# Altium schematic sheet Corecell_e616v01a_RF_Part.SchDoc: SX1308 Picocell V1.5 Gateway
size A2; DrawnBy: EMr; DocumentNumber: 2; SheetNumber: 2; SheetTotal: 3; PageSetup: Record=PageOptions¦CenterHorizontal=True¦CenterVertical=True¦PrintScale=0.47¦XCorrection=1.00¦YCorrection=1.00¦PrintKind=0¦BorderSize=5000000¦LeftOffset=0¦BottomOffset=0¦Orientation=2¦PaperLength=1000¦PaperWidth=1000¦Scale=100¦PaperSource=7¦PrintQuality=-4¦MediaType=1¦DitherType=10¦PaperKind=Letter¦PrintScaleMode=1
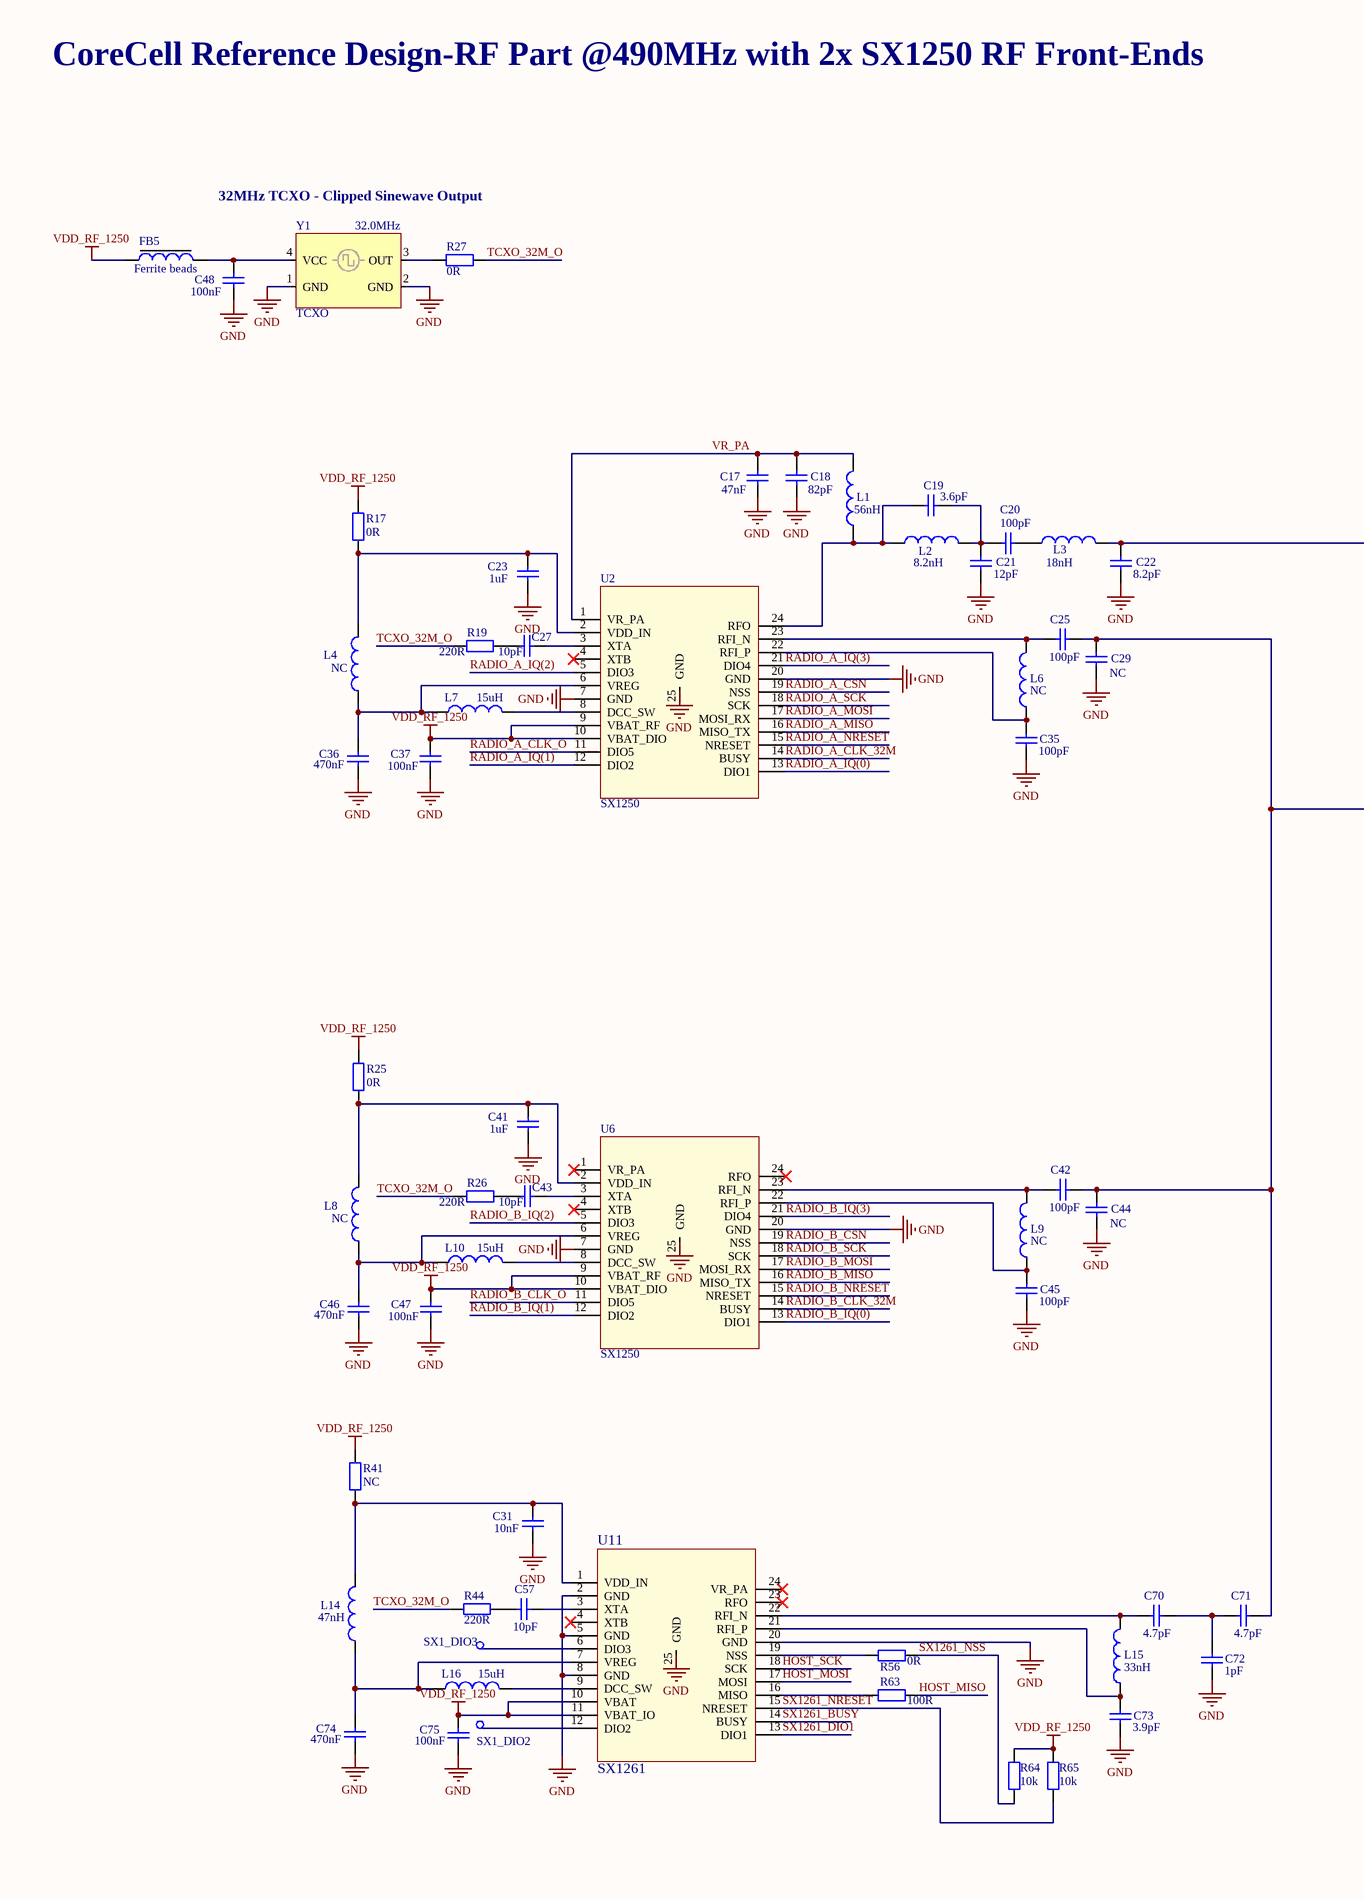
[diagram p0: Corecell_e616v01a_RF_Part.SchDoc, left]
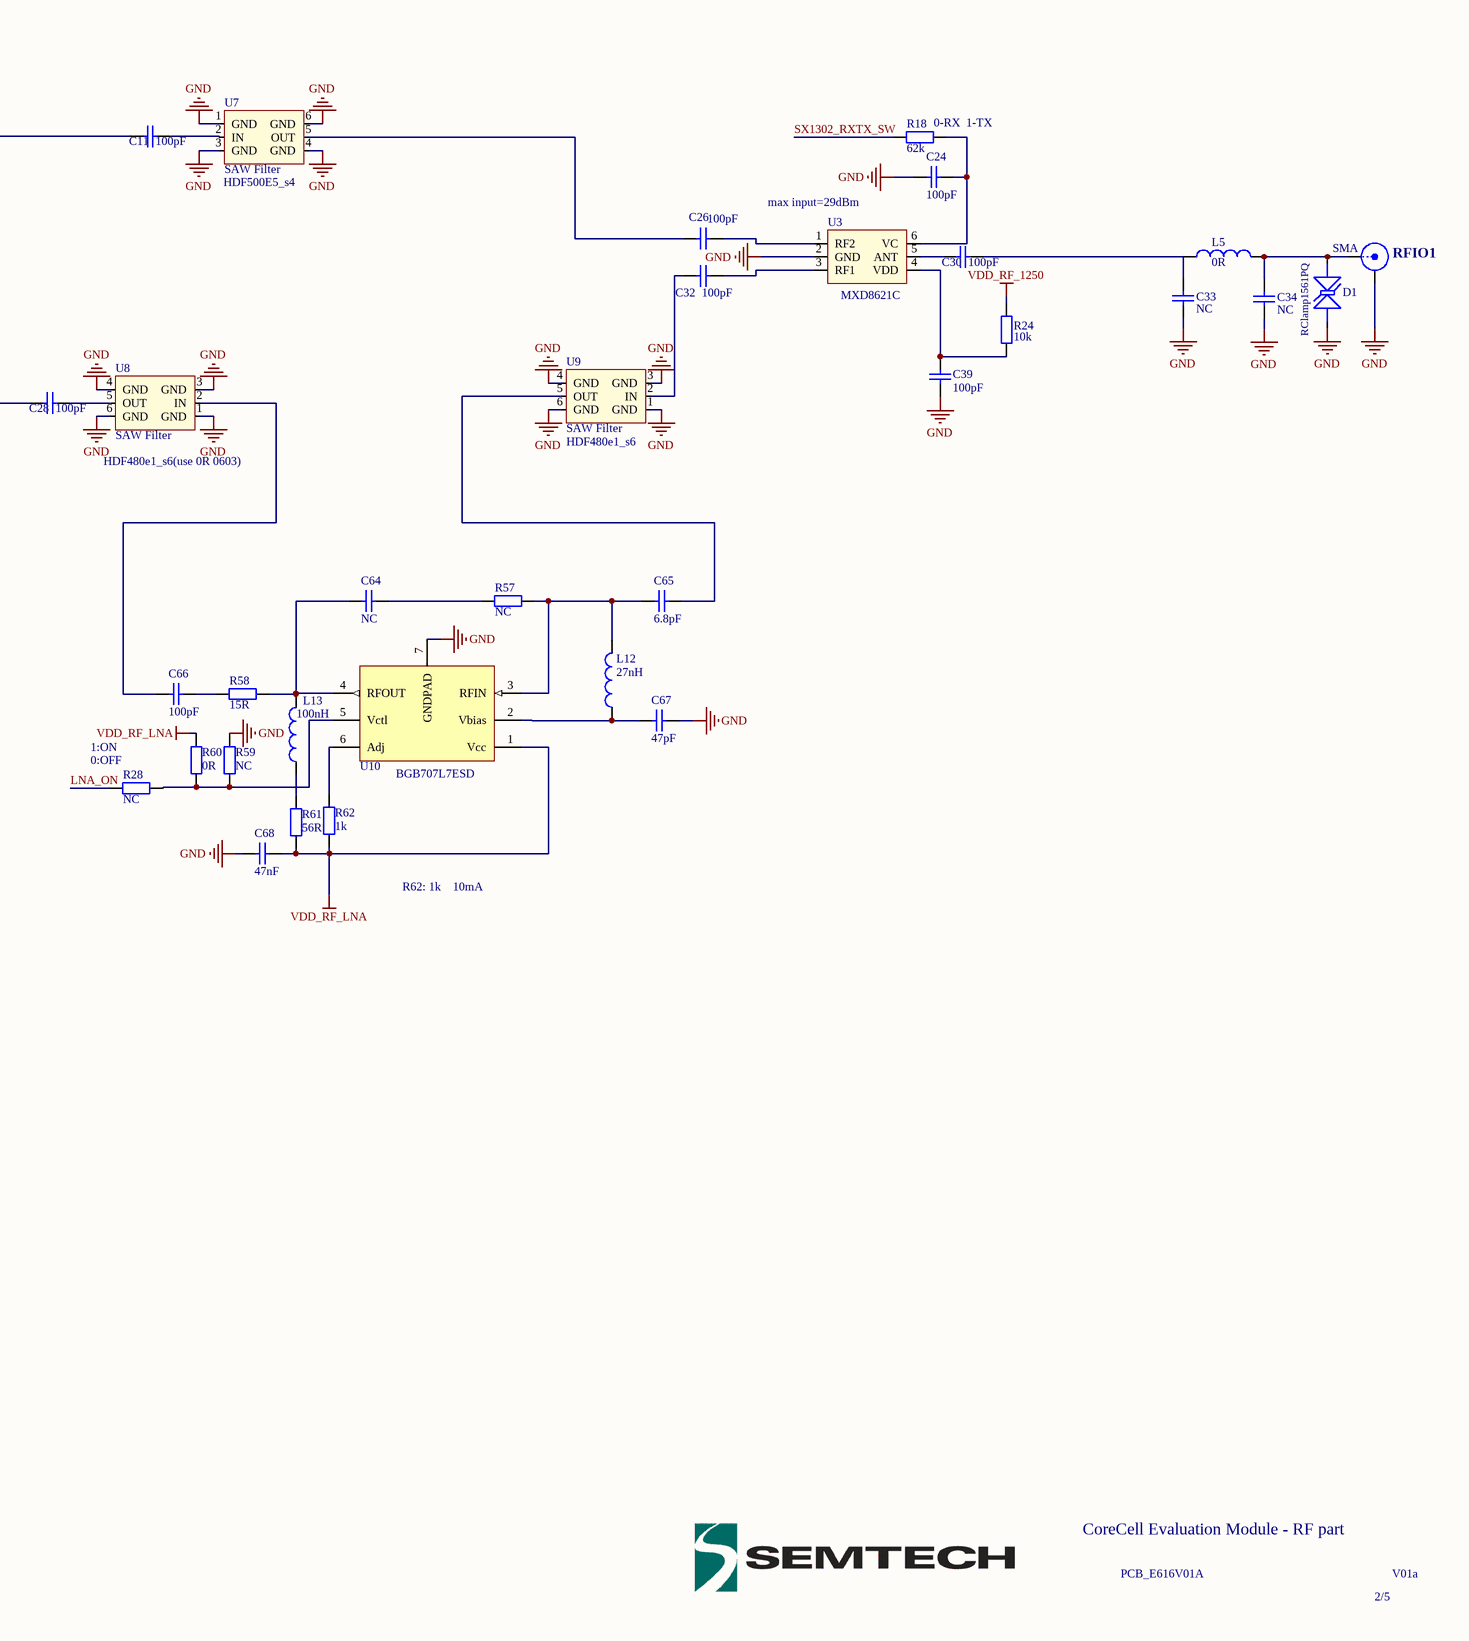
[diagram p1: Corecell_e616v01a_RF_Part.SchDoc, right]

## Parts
C11  value 100pF  [rlc_402_smd_small]  (hidden comment: Cap)
C17  value 47nF  [rlc_402_smd_small]  (hidden comment: Cap)
C18  value 82pF  [rlc_201_smd_small]  (hidden comment: Cap)
C19  value 3.6pF  [rlc_402_smd_small]  (hidden comment: Cap)
C20  value 100pF  [rlc_402_smd_small]  (hidden comment: Cap)
C21  value 12pF  [rlc_402_smd_small]  (hidden comment: Cap)
C22  value 8.2pF  [rlc_402_smd_small]  (hidden comment: Cap)
C23  value 1uF  [rlc_402_smd_small]  (hidden comment: Cap)
C24  value 100pF  [rlc_402_smd_small]  (hidden comment: Cap)
C25  value 100pF  [rlc_402_smd_small]  (hidden comment: Cap)
C26  value 100pF  [rlc_402_smd_small]  (hidden comment: Cap)
C27  value 10pF  [rlc_201_smd_small]  (hidden comment: Cap)
C28  value 100pF  [rlc_402_smd_small]  (hidden comment: Cap)
C29  value NC  [rlc_402_smd_small]  (hidden comment: Cap)
C30  value 100pF  [rlc_402_smd_small]  (hidden comment: Cap)
C31  value 10nF  [rlc_201_smd_small]  (hidden comment: Cap)
C32  value 100pF  [rlc_402_smd_small]  (hidden comment: Cap)
C33  value NC  [rlc_402_smd_small]  (hidden comment: Cap)
C34  value NC  [rlc_402_smd_small]  (hidden comment: Cap)
C35  value 100pF  [rlc_402_smd_small]  (hidden comment: Cap)
C36  value 470nF  [rlc_402_smd_small]  (hidden comment: Cap)
C37  value 100nF  [rlc_201_smd_small]  (hidden comment: Cap)
C39  value 100pF  [rlc_402_smd_small]  (hidden comment: Cap)
C41  value 1uF  [rlc_402_smd_small]  (hidden comment: Cap)
C42  value 100pF  [rlc_402_smd_small]  (hidden comment: Cap)
C43  value 10pF  [rlc_201_smd_small]  (hidden comment: Cap)
C44  value NC  [rlc_402_smd_small]  (hidden comment: Cap)
C45  value 100pF  [rlc_402_smd_small]  (hidden comment: Cap)
C46  value 470nF  [rlc_402_smd_small]  (hidden comment: Cap)
C47  value 100nF  [rlc_201_smd_small]  (hidden comment: Cap)
C48  value 100nF  [rlc_201_smd_small]  (hidden comment: Cap)
C57  value 10pF  [rlc_201_smd_small]  (hidden comment: Cap)
C64  value NC  [rlc_402_smd_small]  (hidden comment: Cap)
C65  value 6.8pF  [rlc_402_smd_small]  (hidden comment: Cap)
C66  value 100pF  [rlc_402_smd_small]  (hidden comment: Cap)
C67  value 47pF  [rlc_402_smd_small]  (hidden comment: Cap)
C68  value 47nF  [rlc_402_smd_small]  (hidden comment: Cap)
C70  value 4.7pF  [rlc_201_smd_small]  (hidden comment: Cap)
C71  value 4.7pF  [rlc_201_smd_small]  (hidden comment: Cap)
C72  value 1pF  [rlc_201_smd_small]  (hidden comment: Cap)
C73  value 3.9pF  [rlc_201_smd_small]  (hidden comment: Cap)
C74  value 470nF  [rlc_402_smd_small]  (hidden comment: Cap)
C75  value 100nF  [rlc_201_smd_small]  (hidden comment: Cap)
D1  RClamp1561PQ  [SLP1006P2]
FB5  Ferrite beads  [rlc_402_smd_small]
L1  value 56nH  [rlc_402_smd_small]  (hidden comment: Inductor)
L2  value 8.2nH  [rlc_402_smd_small]  (hidden comment: Inductor)
L3  value 18nH  [rlc_402_smd_small]  (hidden comment: Inductor)
L4  value NC  [rlc_402_smd_small]  (hidden comment: Inductor)
L5  value 0R  [rlc_402_smd_small]  (hidden comment: Inductor)
L6  value NC  [rlc_402_smd_small]  (hidden comment: Inductor)
L7  value 15uH  [rlc_805_smd_small]  (hidden comment: Inductor)
L8  value NC  [rlc_402_smd_small]  (hidden comment: Inductor)
L9  value NC  [rlc_402_smd_small]  (hidden comment: Inductor)
L10  value 15uH  [rlc_805_smd_small]  (hidden comment: Inductor)
L12  value 27nH  [rlc_402_smd_small]  (hidden comment: Inductor)
L13  value 100nH  [rlc_402_smd_small]  (hidden comment: Inductor)
L14  value 47nH  [rlc_402_smd_small]  (hidden comment: Inductor)
L15  value 33nH  [rlc_402_smd_small]  (hidden comment: Inductor)
L16  value 15uH  [rlc_805_smd_small]  (hidden comment: Inductor)
R17  value 0R  [rlc_402_smd_small]  (hidden comment: Resistor)
R18  value 62k  [rlc_402_smd_small]  (hidden comment: Resistor)
R19  value 220R  [rlc_201_smd_small]  (hidden comment: Resistor)
R24  value 10k  [rlc_402_smd_small]  (hidden comment: Resistor)
R25  value 0R  [rlc_402_smd_small]  (hidden comment: Resistor)
R26  value 220R  [rlc_201_smd_small]  (hidden comment: Resistor)
R27  value 0R  [rlc_201_smd_small]  (hidden comment: Resistor)
R28  value NC  [rlc_402_smd_small]  (hidden comment: Resistor)
R41  value NC  [rlc_201_smd_small]  (hidden comment: Resistor)
R44  value 220R  [rlc_201_smd_small]  (hidden comment: Resistor)
R56  value 0R  [rlc_201_smd_small]  (hidden comment: Resistor)
R57  value NC  [rlc_402_smd_small]  (hidden comment: Resistor)
R58  value 15R  [rlc_402_smd_small]  (hidden comment: Resistor)
R59  value NC  [rlc_402_smd_small]  (hidden comment: Resistor)
R60  value 0R  [rlc_402_smd_small]  (hidden comment: Resistor)
R61  value 56R  [rlc_402_smd_small]  (hidden comment: Resistor)
R62  value 1k  [rlc_402_smd_small]  (hidden comment: Resistor)
R63  value 100R  [rlc_201_smd_small]  (hidden comment: Resistor)
R64  value 10k  [rlc_201_smd_small]  (hidden comment: Resistor)
R65  value 10k  [rlc_201_smd_small]  (hidden comment: Resistor)
RFIO1  SMA  [SMA_end_launch_1.6mm_6.35mm]
SX1_DIO2  Test Pin  [PIN_SMD]  (value not drawn)
SX1_DIO3  Test Pin  [PIN_SMD]  (value not drawn)
U2  SX1250  [vqfn24_4x4mm]
U3  MXD8621C  [DFN_6]
U6  SX1250  [vqfn24_4x4mm]
U7  SAW Filter  value HDF500E5_s4  [DCC6C_3.8x3.8mm]
U8  SAW Filter  value HDF480e1_s6(use 0R 0603)  [DCC6C_3.0x3.0mm]
U9  SAW Filter  value HDF480e1_s6  [DCC6C_3.0x3.0mm]
U10  BGB707L7ESD  [TSLP-7-1]
U11  SX1261  [vqfn24_4x4mm]
Y1  TCXO  value 32.0MHz  [TCXO 2.0x1.6mm]

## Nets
GND: C17.1 C18.1 C21.1 C22.1 C23.1 C24.1 C29.1 C31.1 C33.2 C34.2 C35.1 C36.1 C37.1 C39.2 C41.1 C44.1 C45.1 C46.1 C47.1 C48.1 C67.1 C68.2 C72.1 C73.1 C74.1 C75.1 D1.2(K) R59.2 RFIO1.2(GND) U2.7(GND) U2.20(GND) U2.25(GND) U3.2(GND) U6.7(GND) U6.20(GND) U6.25(GND) U7.1(GND) U7.3(GND) U7.4(GND) U7.6(GND) U8.1(GND) U8.3(GND) U8.4(GND) U8.6(GND) U9.1(GND) U9.3(GND) U9.4(GND) U9.6(GND) U10.7(GNDPAD) U11.2(GND) U11.5(GND) U11.8(GND) U11.20(GND) U11.25(GND) Y1.1(GND) Y1.2(GND)
VDD_RF_1250: C37.2 C47.2 C75.2 FB5.1 R17.1 R24.2 R25.1 R41.1 R64.1 R65.1 U2.9(VBAT_RF) U2.10(VBAT_DIO) U6.9(VBAT_RF) U6.10(VBAT_DIO) U11.10(VBAT) U11.11(VBAT_IO)
VDD_RF_LNA: C68.1 R60.2 R61.2 R62.2 U10.1(Vcc)
HOST_MISO: R63.2
HOST_MOSI: U11.17(MOSI)
HOST_SCK: U11.18(SCK)
LNA_ON: R28.2
RADIO_A_CLK_32M: U2.14(BUSY)
RADIO_A_CLK_O: U2.11(DIO5)
RADIO_A_CSN: U2.19(NSS)
RADIO_A_IQ(0): U2.13(DIO1)
RADIO_A_IQ(1): U2.12(DIO2)
RADIO_A_IQ(2): U2.5(DIO3)
RADIO_A_IQ(3): U2.21(DIO4)
RADIO_A_MISO: U2.16(MISO_TX)
RADIO_A_MOSI: U2.17(MOSI_RX)
RADIO_A_NRESET: U2.15(NRESET)
RADIO_A_SCK: U2.18(SCK)
RADIO_B_CLK_32M: U6.14(BUSY)
RADIO_B_CLK_O: U6.11(DIO5)
RADIO_B_CSN: U6.19(NSS)
RADIO_B_IQ(0): U6.13(DIO1)
RADIO_B_IQ(1): U6.12(DIO2)
RADIO_B_IQ(2): U6.5(DIO3)
RADIO_B_IQ(3): U6.21(DIO4)
RADIO_B_MISO: U6.16(MISO_TX)
RADIO_B_MOSI: U6.17(MOSI_RX)
RADIO_B_NRESET: U6.15(NRESET)
RADIO_B_SCK: U6.18(SCK)
SX1261_BUSY: U11.14(BUSY)
SX1261_DIO1: U11.13(DIO1)
SX1261_NRESET: R65.2 U11.15(NRESET)
SX1261_NSS: R56.2 R64.2
SX1302_RXTX_SW: R18.2
TCXO_32M_O: R19.2 R26.2 R27.1 R44.2
VR_PA: C17.2 C18.2 L1.2 U2.1(VR_PA)
NetC11_1: C11.1 C22.2 L3.2
NetC11_2: C11.2 U7.2(IN)
NetC19_1: C19.1 C20.2 C21.2 L2.2
NetC19_2: C19.2 L1.1 L2.1 U2.24(RFO)
NetC20_1: C20.1 L3.1
NetC23_2: C23.2 L4.1 R17.2 U2.2(VDD_IN)
NetC24_2: C24.2 R18.1 U3.6(VC)
NetC25_1: C25.1 C28.1 C29.2 C42.1 C44.2 C71.1
NetC25_2: C25.2 L6.2 U2.23(RFI_N)
NetC26_1: C26.1 U7.5(OUT)
NetC26_2: C26.2 U3.1(RF2)
NetC27_1: C27.1 U2.3(XTA)
NetC27_2: C27.2 R19.1
NetC28_2: C28.2 U8.5(OUT)
NetC30_1: C30.1 U3.5(ANT)
NetC30_2: C30.2 C33.1 L5.1
NetC31_2: C31.2 L14.1 R41.2 U11.1(VDD_IN)
NetC32_1: C32.1 U9.2(IN)
NetC32_2: C32.2 U3.3(RF1)
NetC34_1: C34.1 D1.1(A) L5.2 RFIO1.1(Signal)
NetC35_2: C35.2 L6.1 U2.22(RFI_P)
NetC36_2: C36.2 L4.2 L7.1 U2.6(VREG)
NetC39_1: C39.1 R24.1 U3.4(VDD)
NetC41_2: C41.2 L8.1 R25.2 U6.2(VDD_IN)
NetC42_2: C42.2 L9.2 U6.23(RFI_N)
NetC43_1: C43.1 U6.3(XTA)
NetC43_2: C43.2 R26.1
NetC45_2: C45.2 L9.1 U6.22(RFI_P)
NetC46_2: C46.2 L8.2 L10.1 U6.6(VREG)
NetC48_2: C48.2 FB5.2 Y1.4(VCC)
NetC57_1: C57.1 U11.3(XTA)
NetC57_2: C57.2 R44.1
NetC64_1: C64.1 R57.2
NetC64_2: C64.2 L13.2 R58.1 U10.4(RFOUT)
NetC65_1: C65.1 U9.5(OUT)
NetC65_2: C65.2 L12.2 R57.1 U10.3(RFIN)
NetC66_1: C66.1 R58.2
NetC66_2: C66.2 U8.2(IN)
NetC67_2: C67.2 L12.1 U10.2(Vbias)
NetC70_1: C70.1 C71.2 C72.2
NetC70_2: C70.2 L15.2 U11.22(RFI_N)
NetC73_2: C73.2 L15.1 U11.21(RFI_P)
NetC74_2: C74.2 L14.2 L16.1 U11.7(VREG)
NetL7_2: L7.2 U2.8(DCC_SW)
NetL10_2: L10.2 U6.8(DCC_SW)
NetL13_1: L13.1 R61.1
NetL16_2: L16.2 U11.9(DCC_SW)
NetR27_2: R27.2 Y1.3(OUT)
NetR28_1: R28.1 R59.1 R60.1 U10.5(Vctl)
NetR56_1: R56.1 U11.19(NSS)
NetR62_1: R62.1 U10.6(Adj)
NetR63_1: R63.1 U11.16(MISO)
NetSX1_DIO2_1: SX1_DIO2.1(pin) U11.12(DIO2)
NetSX1_DIO3_1: SX1_DIO3.1(pin) U11.6(DIO3)

Not connected (* = marked no-connect by the designer): U2 4(XTB)*; U6 1(VR_PA)* 4(XTB)* 24(RFO)*; U11 4(XTB)* 23(RFO)* 24(VR_PA)*

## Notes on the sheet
- CoreCell Reference Design-RF Part @490MHz with 2x SX1250 RF Front-Ends
- 32MHz TCXO - Clipped Sinewave Output
- (near R18) 0-RX  1-TX
- (near U3) max input=29dBm
- (near R28) 1:ON
- (near R28) 0:OFF
- R62:
- 1k    10mA
- CoreCell Evaluation Module - RF part
- PCB_E616V01A
- 2/5
- V01a

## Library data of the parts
C11 C17-C37 C39 C41-C48 C57 C64-C68 C70-C75 = Cap: Capacitor SMD
D1 = RClamp0531T: Ultra Low Capacitance 1-line ESD Protection
FB5 = Ferrite beads: Value: 10R @100MHz
L1-L10 L12-L16 = Inductor: Code_IEC: 1005
R17-R19 R24-R28 R41 R44 R56-R65 = Resistor: Resistor SMD - IEC symbol version
RFIO1 = SMA: SMA Straight Connector; Value: SMA-KE11
SX1_DIO2 SX1_DIO3 = test_pin
U2 U6 = SX1250: SX1250 - Ultra low power RF Front-End
U3 = MXD8621C Switch
U7-U9 = SAW Filter: SAW Filter - Bandpass - TEMEX type
U10 = BGB707L7ESD: LAN,Adjustable gain; Manufacturer: Infineon; F (typ): 1.2 dB; Frequency (f): 10MHz - 1000MHz; Gain (typ): 13.5 dB; Green: yes; I (typ): 2.8 mA; P-1dB (out): 6.0 dBm; Value: BGB719N7ESD
U11 = SX126x: SX1261/2 - Ultra low power RF transceiver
